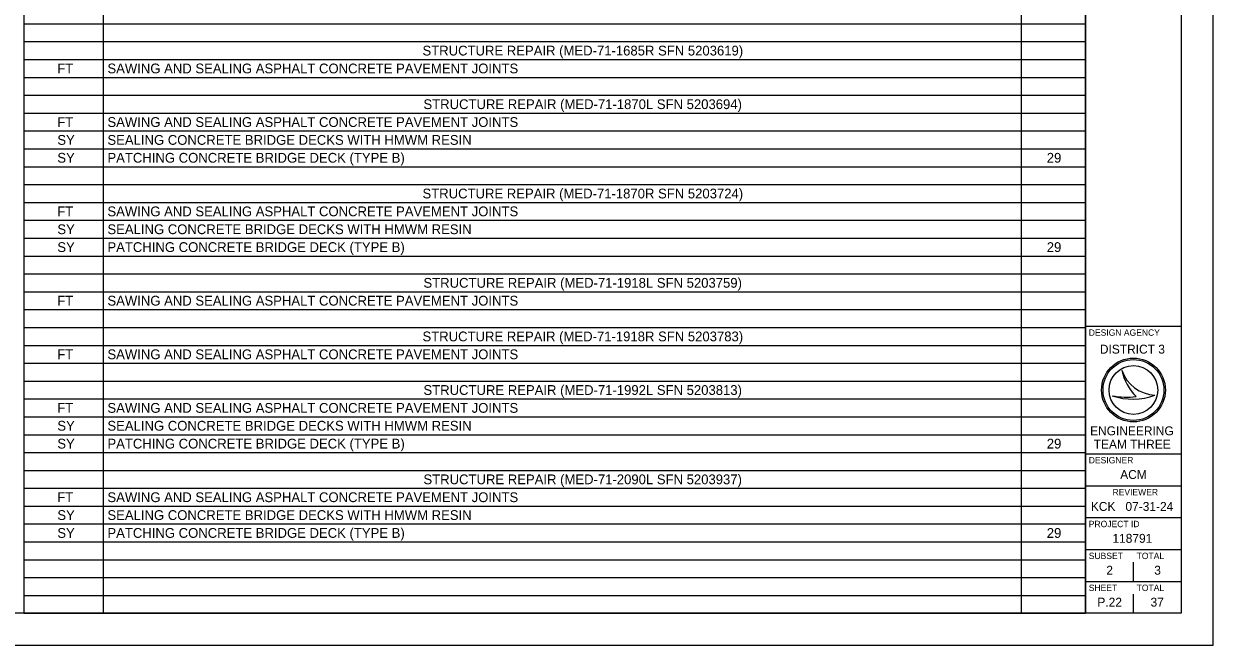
# Model space of a CAD drawing. Extents: x 0 to 34, y 0 to 22.
# Drawn here: x 15.36 to 34, y 0 to 9.74 of the extents above; entities that cross this region are included whole.
import ezdxf

# ---------------------------------------------------------------- set-up
doc = ezdxf.new("R2010")
doc.units = 0
for name, color, linetype in [('SH_Border', 7, 'Continuous'), ('SH_Cut_Line', 7, 'Continuous'), ('SH_Data', 7, 'Continuous'), ('SH_Text', 7, 'Continuous')]:
    doc.layers.add(name, color=color, linetype=linetype)

msp = doc.modelspace()

# ---------------------------------------------------------------- linework, layer by layer
at = {"layer": 'SH_Border'}
for p, q in [((32, 0.5), (32, 21.5)), ((32, 5), (33.5, 5)), ((32, 3), (33.5, 3)), ((32, 2.5), (33.5, 2.5)), ((32, 2), (33.5, 2)), ((32, 1.5), (33.5, 1.5)), ((32, 1), (33.5, 1))]:
    msp.add_line(p, q, dxfattribs=at)
msp.add_lwpolyline([(1.5, 21.5), (33.5, 21.5), (33.5, 0.5), (1.5, 0.5)], close=True, dxfattribs=at)
at = {"layer": 'SH_Cut_Line'}
msp.add_lwpolyline([(0, 0), (34, 0), (34, 22), (0, 22)], close=True, dxfattribs=at)
at = {"layer": 'SH_Data'}
for p, q in [((32.567, 4.31), (32.567, 4.31)), ((32.75, 4), (32.75, 4)), ((33.087, 3.919), (33.087, 3.919)), ((32.417, 3.91), (32.417, 3.91)), ((32.75, 1), (32.75, 1.3)), ((32.75, 0.5), (32.75, 0.8)), ((32.375, 0.675), (32.375, 0.675))]:
    msp.add_line(p, q, dxfattribs=at)
for radius in [0.5, 0.477, 0.477, 0.382]:
    msp.add_circle((32.75, 4), radius, dxfattribs=at)
for centre, radius, start, end in [((33.116, 4.498), 0.58, 198.9257, 198.9319), ((33.347, 4.47), 0.796, 191.6379, 191.6421), ((33.116, 4.498), 0.58, 198.9319, 267.1657), ((33.347, 4.47), 0.796, 191.6421, 226.0947), ((32.739, 4.87), 1.013, 251.4576, 290.0832), ((32.648, 5.154), 1.266, 259.4964, 259.4995), ((32.739, 4.87), 1.013, 251.4527, 251.4576), ((32.648, 5.154), 1.266, 259.4995, 276.6672)]:
    msp.add_arc(centre, radius, start, end, dxfattribs=at)
at = {"layer": 'SH_Text'}
for p, q in [((15.361, 10.02), (15.361, 9.74)), ((16.607, 10.02), (16.607, 9.74)), ((30.988, 10.02), (30.988, 9.74)), ((32, 10.02), (32, 9.74)), ((15.361, 9.74), (16.607, 9.74)), ((15.361, 9.74), (15.361, 8.9)), ((16.607, 9.74), (30.988, 9.74)), ((16.607, 9.74), (16.607, 8.9)), ((30.988, 9.74), (32, 9.74)), ((30.988, 9.74), (30.988, 8.9)), ((32, 9.74), (32, 8.9)), ((15.361, 9.46), (16.607, 9.46)), ((16.607, 9.46), (30.988, 9.46)), ((30.988, 9.46), (32, 9.46)), ((15.361, 9.18), (16.607, 9.18)), ((16.607, 9.18), (30.988, 9.18)), ((30.988, 9.18), (32, 9.18)), ((15.361, 8.9), (16.607, 8.9)), ((15.361, 8.9), (15.361, 8.34)), ((16.607, 8.9), (30.988, 8.9)), ((16.607, 8.9), (16.607, 8.34)), ((30.988, 8.9), (32, 8.9)), ((30.988, 8.9), (30.988, 8.34)), ((32, 8.9), (32, 8.34)), ((15.361, 8.62), (16.607, 8.62)), ((16.607, 8.62), (30.988, 8.62)), ((30.988, 8.62), (32, 8.62)), ((15.361, 8.34), (16.607, 8.34)), ((15.361, 8.34), (15.361, 7.5)), ((16.607, 8.34), (30.988, 8.34)), ((16.607, 8.34), (16.607, 7.5)), ((30.988, 8.34), (32, 8.34)), ((30.988, 8.34), (30.988, 7.5)), ((32, 8.34), (32, 7.5)), ((15.361, 8.06), (16.607, 8.06)), ((16.607, 8.06), (30.988, 8.06)), ((30.988, 8.06), (32, 8.06)), ((15.361, 7.78), (16.607, 7.78)), ((16.607, 7.78), (30.988, 7.78)), ((30.988, 7.78), (32, 7.78)), ((15.361, 7.5), (16.607, 7.5)), ((15.361, 7.5), (15.361, 6.94)), ((16.607, 7.5), (30.988, 7.5)), ((16.607, 7.5), (16.607, 6.94)), ((30.988, 7.5), (32, 7.5)), ((30.988, 7.5), (30.988, 6.94)), ((32, 7.5), (32, 6.94)), ((15.361, 7.22), (16.607, 7.22)), ((16.607, 7.22), (30.988, 7.22)), ((30.988, 7.22), (32, 7.22)), ((15.361, 6.94), (16.607, 6.94)), ((15.361, 6.94), (15.361, 6.1)), ((16.607, 6.94), (30.988, 6.94)), ((16.607, 6.94), (16.607, 6.1)), ((30.988, 6.94), (32, 6.94)), ((30.988, 6.94), (30.988, 6.1)), ((32, 6.94), (32, 6.1)), ((15.361, 6.66), (16.607, 6.66)), ((16.607, 6.66), (30.988, 6.66)), ((30.988, 6.66), (32, 6.66)), ((15.361, 6.38), (16.607, 6.38)), ((16.607, 6.38), (30.988, 6.38)), ((30.988, 6.38), (32, 6.38)), ((15.361, 6.1), (16.607, 6.1)), ((15.361, 6.1), (15.361, 4.98)), ((16.607, 6.1), (30.988, 6.1)), ((16.607, 6.1), (16.607, 4.98)), ((30.988, 6.1), (32, 6.1)), ((30.988, 6.1), (30.988, 4.98)), ((32, 6.1), (32, 4.98)), ((15.361, 5.82), (16.607, 5.82)), ((16.607, 5.82), (30.988, 5.82)), ((30.988, 5.82), (32, 5.82)), ((15.361, 5.54), (16.607, 5.54)), ((16.607, 5.54), (30.988, 5.54)), ((30.988, 5.54), (32, 5.54)), ((15.361, 5.26), (16.607, 5.26)), ((16.607, 5.26), (30.988, 5.26)), ((30.988, 5.26), (32, 5.26)), ((15.361, 4.98), (16.607, 4.98)), ((15.361, 4.98), (15.361, 4.7)), ((16.607, 4.98), (30.988, 4.98)), ((16.607, 4.98), (16.607, 4.7)), ((30.988, 4.98), (32, 4.98)), ((30.988, 4.98), (30.988, 4.7)), ((32, 4.98), (32, 4.7)), ((15.361, 4.7), (16.607, 4.7)), ((15.361, 4.7), (15.361, 3.58)), ((16.607, 4.7), (30.988, 4.7)), ((16.607, 4.7), (16.607, 3.58)), ((30.988, 4.7), (32, 4.7)), ((30.988, 4.7), (30.988, 3.58)), ((32, 4.7), (32, 3.58)), ((15.361, 4.42), (16.607, 4.42)), ((16.607, 4.42), (30.988, 4.42)), ((30.988, 4.42), (32, 4.42)), ((15.361, 4.14), (16.607, 4.14)), ((16.607, 4.14), (30.988, 4.14)), ((30.988, 4.14), (32, 4.14)), ((15.361, 3.86), (16.607, 3.86)), ((16.607, 3.86), (30.988, 3.86)), ((30.988, 3.86), (32, 3.86)), ((15.361, 3.58), (16.607, 3.58)), ((15.361, 3.58), (15.361, 3.3)), ((16.607, 3.58), (30.988, 3.58)), ((16.607, 3.58), (16.607, 3.3)), ((30.988, 3.58), (32, 3.58)), ((30.988, 3.58), (30.988, 3.3)), ((32, 3.58), (32, 3.3)), ((15.361, 3.3), (16.607, 3.3)), ((15.361, 3.3), (15.361, 2.18)), ((16.607, 3.3), (30.988, 3.3)), ((16.607, 3.3), (16.607, 2.18)), ((30.988, 3.3), (32, 3.3)), ((30.988, 3.3), (30.988, 2.18)), ((32, 3.3), (32, 2.18)), ((15.361, 3.02), (16.607, 3.02)), ((16.607, 3.02), (30.988, 3.02)), ((30.988, 3.02), (32, 3.02)), ((15.361, 2.74), (16.607, 2.74)), ((16.607, 2.74), (30.988, 2.74)), ((30.988, 2.74), (32, 2.74)), ((15.361, 2.46), (16.607, 2.46)), ((16.607, 2.46), (30.988, 2.46)), ((30.988, 2.46), (32, 2.46)), ((15.361, 2.18), (16.607, 2.18)), ((15.361, 2.18), (15.361, 1.9)), ((16.607, 2.18), (30.988, 2.18)), ((16.607, 2.18), (16.607, 1.9)), ((30.988, 2.18), (32, 2.18)), ((30.988, 2.18), (30.988, 1.9)), ((32, 2.18), (32, 1.9)), ((15.361, 1.9), (16.607, 1.9)), ((15.361, 1.9), (15.361, 0.78)), ((16.607, 1.9), (30.988, 1.9)), ((16.607, 1.9), (16.607, 0.78)), ((30.988, 1.9), (32, 1.9)), ((30.988, 1.9), (30.988, 0.78)), ((32, 1.9), (32, 0.78)), ((15.361, 1.62), (16.607, 1.62)), ((16.607, 1.62), (30.988, 1.62)), ((30.988, 1.62), (32, 1.62)), ((15.361, 1.34), (16.607, 1.34)), ((16.607, 1.34), (30.988, 1.34)), ((30.988, 1.34), (32, 1.34)), ((15.361, 1.06), (16.607, 1.06)), ((16.607, 1.06), (30.988, 1.06)), ((30.988, 1.06), (32, 1.06)), ((15.361, 0.78), (16.607, 0.78)), ((15.361, 0.78), (15.361, 0.5)), ((16.607, 0.78), (30.988, 0.78)), ((16.607, 0.78), (16.607, 0.5)), ((30.988, 0.78), (32, 0.78)), ((30.988, 0.78), (30.988, 0.5)), ((32, 0.78), (32, 0.5)), ((15.361, 0.5), (16.607, 0.5)), ((16.607, 0.5), (30.988, 0.5)), ((30.988, 0.5), (32, 0.5))]:
    msp.add_line(p, q, dxfattribs=at)

# ---------------------------------------------------------------- texts
at = {"layer": 'SH_Data'}
for s, height, p in [('DESIGN AGENCY', 0.1, (32.05, 4.85)), ('DISTRICT 3', 0.14, (32.224, 4.57)), ('ENGINEERING', 0.14, (32.071, 3.29)), ('TEAM THREE', 0.14, (32.127, 3.08)), ('DESIGNER', 0.1, (32.05, 2.85)), ('ACM', 0.14, (32.543, 2.605)), ('REVIEWER', 0.1, (32.422, 2.35)), ('KCK', 0.14, (32.083, 2.105)), ('07-31-24', 0.14, (32.625, 2.105)), ('PROJECT ID', 0.1, (32.05, 1.85)), ('SUBSET', 0.1, (32.05, 1.35)), ('TOTAL', 0.1, (32.8, 1.35)), ('2', 0.14, (32.325, 1.105)), ('3', 0.14, (33.076, 1.105)), ('SHEET', 0.1, (32.05, 0.85)), ('TOTAL', 0.1, (32.8, 0.85)), ('P.22', 0.14, (32.185, 0.605)), ('37', 0.14, (33.018, 0.605))]:
    msp.add_text(s, height=height, dxfattribs=at).set_placement(p)
at = {"layer": 'SH_Text'}
for s, height, p in [('STRUCTURE REPAIR (MED-71-1685R SFN 5203619)', 0.15333, (21.609, 9.243)), ('FT', 0.1533, (15.885, 8.963)), ('SAWING AND SEALING ASPHALT CONCRETE PAVEMENT JOINTS', 0.15333, (16.672, 8.963)), ('STRUCTURE REPAIR (MED-71-1870L SFN 5203694)', 0.15333, (21.624, 8.403)), ('FT', 0.1533, (15.885, 8.123)), ('SAWING AND SEALING ASPHALT CONCRETE PAVEMENT JOINTS', 0.15333, (16.672, 8.123)), ('SY', 0.1533, (15.887, 7.843)), ('SEALING CONCRETE BRIDGE DECKS WITH HMWM RESIN', 0.15333, (16.672, 7.843)), ('SY', 0.1533, (15.887, 7.563)), ('PATCHING CONCRETE BRIDGE DECK (TYPE B)', 0.15333, (16.672, 7.563)), ('29', 0.1533, (31.392, 7.563)), ('STRUCTURE REPAIR (MED-71-1870R SFN 5203724)', 0.15333, (21.609, 7.003)), ('FT', 0.1533, (15.885, 6.723)), ('SAWING AND SEALING ASPHALT CONCRETE PAVEMENT JOINTS', 0.15333, (16.672, 6.723)), ('SY', 0.1533, (15.887, 6.443)), ('SEALING CONCRETE BRIDGE DECKS WITH HMWM RESIN', 0.15333, (16.672, 6.443)), ('SY', 0.1533, (15.887, 6.163)), ('PATCHING CONCRETE BRIDGE DECK (TYPE B)', 0.15333, (16.672, 6.163)), ('29', 0.1533, (31.392, 6.163)), ('STRUCTURE REPAIR (MED-71-1918L SFN 5203759)', 0.15333, (21.624, 5.603)), ('FT', 0.1533, (15.885, 5.323)), ('SAWING AND SEALING ASPHALT CONCRETE PAVEMENT JOINTS', 0.15333, (16.672, 5.323)), ('STRUCTURE REPAIR (MED-71-1918R SFN 5203783)', 0.15333, (21.609, 4.763)), ('FT', 0.1533, (15.885, 4.483)), ('SAWING AND SEALING ASPHALT CONCRETE PAVEMENT JOINTS', 0.15333, (16.672, 4.483)), ('STRUCTURE REPAIR (MED-71-1992L SFN 5203813)', 0.15333, (21.624, 3.923)), ('FT', 0.1533, (15.885, 3.643)), ('SAWING AND SEALING ASPHALT CONCRETE PAVEMENT JOINTS', 0.15333, (16.672, 3.643)), ('SY', 0.1533, (15.887, 3.363)), ('SEALING CONCRETE BRIDGE DECKS WITH HMWM RESIN', 0.15333, (16.672, 3.363)), ('SY', 0.1533, (15.887, 3.083)), ('PATCHING CONCRETE BRIDGE DECK (TYPE B)', 0.15333, (16.672, 3.083)), ('29', 0.1533, (31.392, 3.083)), ('STRUCTURE REPAIR (MED-71-2090L SFN 5203937)', 0.15333, (21.624, 2.523)), ('FT', 0.1533, (15.885, 2.243)), ('SAWING AND SEALING ASPHALT CONCRETE PAVEMENT JOINTS', 0.15333, (16.672, 2.243)), ('SY', 0.1533, (15.887, 1.963)), ('SEALING CONCRETE BRIDGE DECKS WITH HMWM RESIN', 0.15333, (16.672, 1.963)), ('SY', 0.1533, (15.887, 1.683)), ('PATCHING CONCRETE BRIDGE DECK (TYPE B)', 0.15333, (16.672, 1.683)), ('29', 0.1533, (31.392, 1.683)), ('118791', 0.14, (32.421, 1.605))]:
    msp.add_text(s, height=height, dxfattribs=at).set_placement(p)

doc.saveas('drawing.dxf')
